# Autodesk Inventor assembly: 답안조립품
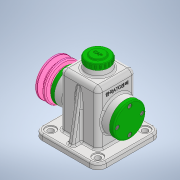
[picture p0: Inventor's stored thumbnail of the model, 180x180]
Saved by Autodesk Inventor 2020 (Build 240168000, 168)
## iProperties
Created: 2021-07
Part Number: 답안조립품
Document SubType Name: Assembly
Designer: Owner
Author: Owner
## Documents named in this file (14)
- C:\Users\Owner\Desktop\710715V1013\답안조립품.iam
- C:\Users\Owner\Desktop\710715V1013\본체.ipt
- C:\Users\Owner\Desktop\710715V1013\710715V1013\V-벨트풀리.ipt
- C:\Users\Owner\Desktop\710715V1013\710715V1013\뒤커버.ipt
- C:\Users\Owner\Desktop\710715V1013\710715V1013\멈춤링 15 x 1.ipt
- C:\Users\Owner\Desktop\710715V1013\710715V1013\베어링 15 x 35 x 11.ipt
- C:\Users\Owner\Desktop\710715V1013\710715V1013\볼트 M4 x 10.ipt
- C:\Users\Owner\Desktop\710715V1013\710715V1013\볼트 M6 x 12.ipt
- C:\Users\Owner\Desktop\710715V1013\710715V1013\상부캡.ipt
- C:\Users\Owner\Desktop\710715V1013\710715V1013\앞커버.ipt
- C:\Users\Owner\Desktop\710715V1013\710715V1013\오일실 15 25 7.ipt
- C:\Users\Owner\Desktop\710715V1013\710715V1013\와셔.ipt
- C:\Users\Owner\Desktop\710715V1013\710715V1013\축.ipt
- C:\Users\Owner\Desktop\710715V1013\710715V1013\키 5 x 5 x 14.ipt
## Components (1 placed, 1 different names)
1. V-벨트풀리:1
